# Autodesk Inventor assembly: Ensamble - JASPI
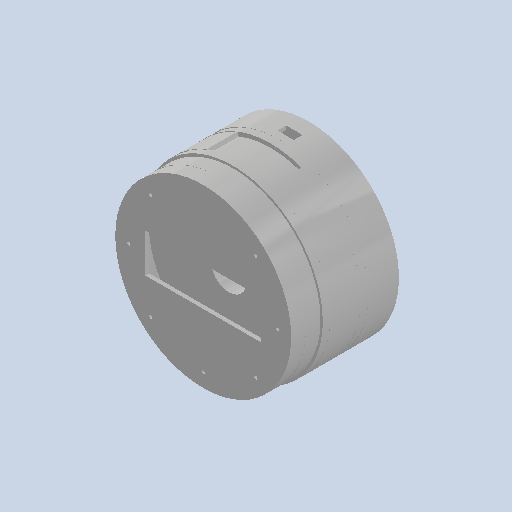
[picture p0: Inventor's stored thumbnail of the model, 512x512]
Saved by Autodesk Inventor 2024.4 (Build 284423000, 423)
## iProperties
Created: 2025-07
Part Number: Ensamble - JASPI
Document SubType Name: Assembly
Designer: AdminForWorker
Title: Ensamble - JASPI v4
Author: AdminForWorker
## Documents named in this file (6)
- c:\worker\convert-fusion-r03-cosv3\tmp\job-1\44\temp\files\cbf4370f-3c06-4583-810b-2f9fedc8fb11\f62c04bb-6733-4738-939d-4d47a36a3227.iam
- c:\worker\convert-fusion-r03-cosv3\tmp\job-1\44\temp\files\cbf4370f-3c06-4583-810b-2f9fedc8fb11\FPGA_Espacio v4.ipt
- c:\worker\convert-fusion-r03-cosv3\tmp\job-1\44\temp\files\cbf4370f-3c06-4583-810b-2f9fedc8fb11\Pastillero - Corazon v7.ipt
- c:\worker\convert-fusion-r03-cosv3\tmp\job-1\44\temp\files\cbf4370f-3c06-4583-810b-2f9fedc8fb11\LCD - Almacen - P2 v5.ipt
- c:\worker\convert-fusion-r03-cosv3\tmp\job-1\44\temp\files\cbf4370f-3c06-4583-810b-2f9fedc8fb11\LCD - Almacen - P1 v8.ipt
- c:\worker\convert-fusion-r03-cosv3\tmp\job-1\44\temp\files\cbf4370f-3c06-4583-810b-2f9fedc8fb11\Deslizante - Corazon v4.ipt
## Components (5 placed, 5 different names)
1. FPGA_Espacio v4:1
2. Pastillero - Corazon v7:1
3. LCD - Almacen - P2 v5:1
4. LCD - Almacen - P1 v8:1
5. Deslizante - Corazon v4:1
